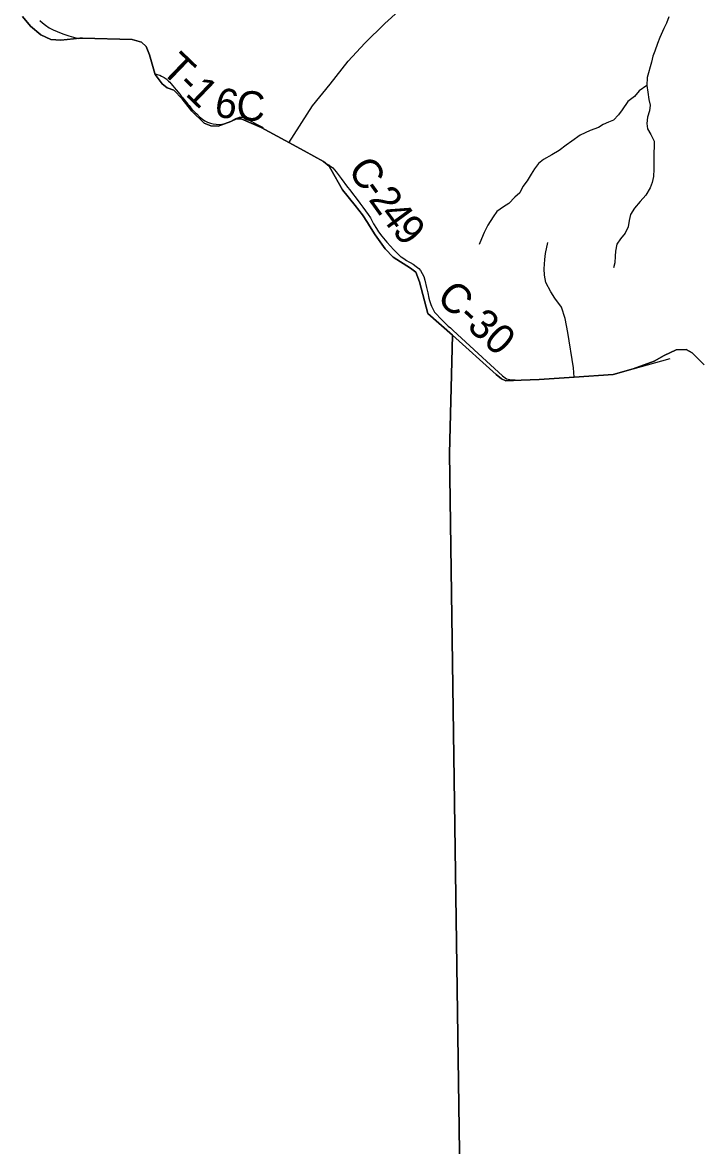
# Model space of a CAD drawing. Extents: x 1578669 to 1989827, y 208020 to 553079.
# Drawn here: x 1745106 to 1751961, y 362639 to 374035 of the extents above; entities that cross this region are included whole.
import ezdxf

# ---------------------------------------------------------------- set-up
doc = ezdxf.new("R2010")
doc.units = 0
for name, color, linetype in [('GM_X_Adjacent_County', 7, 'Continuous'), ('GM_X_County', 7, 'Continuous'), ('GM_X_County_Road', 7, 'Continuous'), ('GM_X_County_Road_Text', 7, 'Continuous'), ('GM_X_Minor_River', 7, 'Continuous'), ('GM_X_State_Route', 7, 'Continuous'), ('GM_X_Township', 7, 'Continuous'), ('GM_X_Township_Road', 7, 'Continuous'), ('GM_X_Township_Road_Text', 7, 'Continuous'), ('GM_X_Township_ROW', 7, 'Continuous')]:
    doc.layers.add(name, color=color, linetype=linetype)

msp = doc.modelspace()

# ---------------------------------------------------------------- linework, layer by layer
at = {"layer": 'GM_X_Adjacent_County'}
for points in [[(1745106, 374096), (1745189, 373999), (1745293, 373911), (1745395, 373862), (1745495, 373856), (1745687, 373875), (1745717, 373877), (1746221, 373861), (1746315, 373836), (1746361, 373792), (1746395, 373706), (1746449, 373518), (1746453, 373506), (1746523, 373413), (1746574, 373371), (1746642, 373350), (1746727, 373259), (1746827, 373134), (1746951, 373014), (1747019, 372987), (1747092, 372984), (1747222, 373031), (1747280, 373056), (1747328, 373058), (1747528, 372969), (1747775, 372836), (1747965, 372734), (1748164, 372623), (1748219, 372578), (1748237, 372547), (1748357, 372338), (1748483, 372177), (1748558, 372085), (1748608, 372006), (1748630, 371972), (1748686, 371882), (1748790, 371739), (1748869, 371654), (1749047, 371541), (1749099, 371501), (1749139, 371405), (1749223, 371083), (1749472, 370863), (1749441, 369663), (1749641, 355723)], [(1749641, 355723), (1749441, 369663), (1749472, 370863), (1749915, 370463), (1749969, 370419), (1750013, 370399), (1750171, 370406), (1750351, 370411), (1750709, 370437), (1751105, 370464), (1751306, 370520), (1751519, 370597), (1751622, 370657), (1751743, 370715), (1751846, 370716), (1751907, 370684), (1752027, 370561)]]:
    msp.add_lwpolyline(points, dxfattribs=at)
at = {"layer": 'GM_X_County'}
msp.add_lwpolyline([(1752027, 370561), (1751907, 370684), (1751846, 370716), (1751743, 370715), (1751622, 370657), (1751519, 370597), (1751306, 370520), (1751105, 370464), (1750709, 370437), (1750351, 370411), (1750171, 370406), (1750013, 370399), (1749969, 370419), (1749915, 370463), (1749472, 370863), (1749223, 371083), (1749139, 371405), (1749099, 371501), (1749047, 371541), (1748869, 371654), (1748790, 371739), (1748686, 371882), (1748630, 371972), (1748608, 372006), (1748558, 372085), (1748483, 372177), (1748357, 372338), (1748237, 372547), (1748219, 372578), (1748164, 372623), (1747965, 372734), (1747775, 372836), (1747528, 372969), (1747328, 373058), (1747280, 373056), (1747222, 373031), (1747092, 372984), (1747019, 372987), (1746951, 373014), (1746827, 373134), (1746727, 373259), (1746642, 373350), (1746574, 373371), (1746523, 373413), (1746453, 373506), (1746449, 373518), (1746395, 373706), (1746361, 373792), (1746315, 373836), (1746221, 373861), (1745717, 373877), (1745687, 373875), (1745495, 373856), (1745395, 373862), (1745293, 373911), (1745189, 373999), (1745106, 374096)], dxfattribs=at)
at = {"layer": 'GM_X_County_Road'}
for points in [[(1745283, 374056), (1745309, 374031), (1745340, 374007), (1745378, 373982), (1745418, 373959), (1745457, 373942), (1745516, 373920), (1745578, 373901), (1745647, 373880), (1745672, 373873)], [(1748256, 372560), (1748291, 372519), (1748342, 372451), (1748407, 372365), (1748429, 372336), (1748457, 372300), (1748493, 372253), (1748533, 372201), (1748563, 372162), (1748616, 372088), (1748639, 372053), (1748658, 372018), (1748671, 371993), (1748701, 371944), (1748722, 371911), (1748755, 371867), (1748806, 371807), (1748843, 371765), (1748874, 371731), (1748896, 371707), (1748910, 371693), (1748929, 371676), (1748946, 371662), (1748951, 371658), (1748977, 371640), (1749007, 371621), (1749030, 371607), (1749044, 371599), (1749072, 371582), (1749105, 371560), (1749130, 371539), (1749149, 371517), (1749166, 371489), (1749180, 371459), (1749192, 371422), (1749210, 371345), (1749221, 371293), (1749232, 371239), (1749240, 371214), (1749253, 371174), (1749260, 371155), (1749275, 371123), (1749291, 371097), (1749309, 371074), (1749347, 371034), (1749378, 371004), (1749406, 370977), (1749429, 370954), (1749451, 370935), (1749478, 370909)], [(1749478, 370909), (1749818, 370600), (1749980, 370449), (1750021, 370420), (1750055, 370411), (1750164, 370406)], [(1750164, 370406), (1750171, 370406), (1750351, 370411), (1750709, 370437), (1751105, 370464), (1751306, 370520), (1751684, 370627)]]:
    msp.add_lwpolyline(points, dxfattribs=at)
at = {"layer": 'GM_X_Minor_River'}
for points in [[(1751669, 374091), (1751644, 374029), (1751618, 373973), (1751578, 373883), (1751553, 373821), (1751527, 373745), (1751508, 373694), (1751494, 373634), (1751449, 373478), (1751447, 373397), (1751456, 373327), (1751466, 373253), (1751478, 373197), (1751473, 373137), (1751453, 373073), (1751446, 373009), (1751454, 372957), (1751488, 372900), (1751521, 372832), (1751519, 372778), (1751517, 372714), (1751516, 372598), (1751518, 372548), (1751513, 372474), (1751501, 372412), (1751481, 372358), (1751436, 372282), (1751378, 372218), (1751319, 372152), (1751281, 372088), (1751267, 372026), (1751256, 371960), (1751226, 371897), (1751177, 371841), (1751141, 371787), (1751127, 371715), (1751124, 371663), (1751120, 371597), (1751106, 371545)], [(1751447, 373397), (1751368, 373340), (1751322, 373284), (1751252, 373232), (1751197, 373150), (1751159, 373097), (1751108, 373043), (1751058, 373025), (1751004, 372999), (1750954, 372970), (1750872, 372940), (1750769, 372891), (1750683, 372831), (1750627, 372791), (1750557, 372736), (1750482, 372692), (1750396, 372644), (1750346, 372605), (1750305, 372551), (1750273, 372497), (1750231, 372429), (1750188, 372371), (1750156, 372307), (1750106, 372263), (1750043, 372198), (1749991, 372164), (1749923, 372118), (1749884, 372062), (1749830, 371979), (1749793, 371903), (1749767, 371839), (1749745, 371783)]]:
    msp.add_lwpolyline(points, dxfattribs=at)
at = {"layer": 'GM_X_State_Route'}
msp.add_lwpolyline([(1747812, 372813), (1748050, 373188), (1748229, 373409), (1748412, 373643), (1748583, 373824), (1748784, 374024), (1749097, 374308)], dxfattribs=at)
at = {"layer": 'GM_X_Township'}
msp.add_lwpolyline([(1752027, 370561), (1751907, 370684), (1751846, 370716), (1751743, 370715), (1751622, 370657), (1751519, 370597), (1751306, 370520), (1751105, 370464), (1750709, 370437), (1750351, 370411), (1750171, 370406), (1750013, 370399), (1749969, 370419), (1749915, 370463), (1749472, 370863), (1749223, 371083), (1749139, 371405), (1749099, 371501), (1749047, 371541), (1748869, 371654), (1748790, 371739), (1748686, 371882), (1748630, 371972), (1748608, 372006), (1748558, 372085), (1748483, 372177), (1748357, 372338), (1748237, 372547), (1748219, 372578), (1748164, 372623), (1747965, 372734), (1747775, 372836), (1747528, 372969), (1747328, 373058), (1747280, 373056), (1747222, 373031), (1747092, 372984), (1747019, 372987), (1746951, 373014), (1746827, 373134), (1746727, 373259), (1746642, 373350), (1746574, 373371), (1746523, 373413), (1746453, 373506), (1746449, 373518), (1746395, 373706), (1746361, 373792), (1746315, 373836), (1746221, 373861), (1745717, 373877), (1745687, 373875), (1745495, 373856), (1745395, 373862), (1745293, 373911), (1745189, 373999), (1745106, 374096)], dxfattribs=at)
at = {"layer": 'GM_X_Township_Road'}
for points in [[(1746451, 373514), (1746462, 373511), (1746475, 373508), (1746487, 373504), (1746501, 373499), (1746519, 373491), (1746545, 373477), (1746566, 373462), (1746590, 373440), (1746601, 373428), (1746612, 373416), (1746633, 373391), (1746667, 373351), (1746703, 373308), (1746719, 373288), (1746728, 373278), (1746744, 373258), (1746786, 373207), (1746799, 373192), (1746817, 373170), (1746843, 373140), (1746861, 373121), (1746875, 373107), (1746905, 373077), (1746933, 373054), (1746958, 373038), (1746984, 373024), (1747014, 373013), (1747043, 373006), (1747072, 373002), (1747102, 373001), (1747131, 373004), (1747163, 373011), (1747197, 373023), (1747224, 373035), (1747274, 373060), (1747284, 373065), (1747294, 373068), (1747303, 373071), (1747311, 373073), (1747319, 373074), (1747327, 373075), (1747337, 373074), (1747348, 373073), (1747359, 373070), (1747370, 373066), (1747387, 373059), (1747401, 373051), (1747435, 373031), (1747458, 373018), (1747476, 373008), (1747501, 372994), (1747524, 372982), (1747550, 372968)], [(1750709, 370437), (1750702, 370531), (1750643, 370889), (1750616, 371032), (1750580, 371145), (1750512, 371239), (1750470, 371301), (1750421, 371398), (1750407, 371472), (1750402, 371537), (1750410, 371630), (1750417, 371692), (1750442, 371803)]]:
    msp.add_lwpolyline(points, dxfattribs=at)
at = {"layer": 'GM_X_Township_ROW'}
msp.add_lwpolyline([(1748212, 372595), (1748228, 372582), (1748243, 372570), (1748256, 372560)], dxfattribs=at)

# ---------------------------------------------------------------- texts
at = {"layer": 'GM_X_County_Road_Text'}
for s, rotation, p in [('C', 305.7023, (1748400, 372537)), ('2', 305.7084, (1748614, 372239)), ('-', 305.7036, (1748543, 372338)), ('4', 306.1768, (1748723, 372088)), ('9', 311.4892, (1748850, 371916)), ('C-30', 317.4624, (1749297, 371226))]:
    msp.add_text(s, height=300, rotation=rotation, dxfattribs=at).set_placement(p)
at = {"layer": 'GM_X_Township_Road_Text'}
for s, rotation, p in [('T', 316.1413, (1746502, 373543)), ('-', 316.142, (1746663, 373388)), ('1', 316.168, (1746751, 373303)), ('6', 347.4731, (1747039, 373093)), ('C', 357.3636, (1747274, 373045))]:
    msp.add_text(s, height=300, rotation=rotation, dxfattribs=at).set_placement(p)

doc.saveas('drawing.dxf')
